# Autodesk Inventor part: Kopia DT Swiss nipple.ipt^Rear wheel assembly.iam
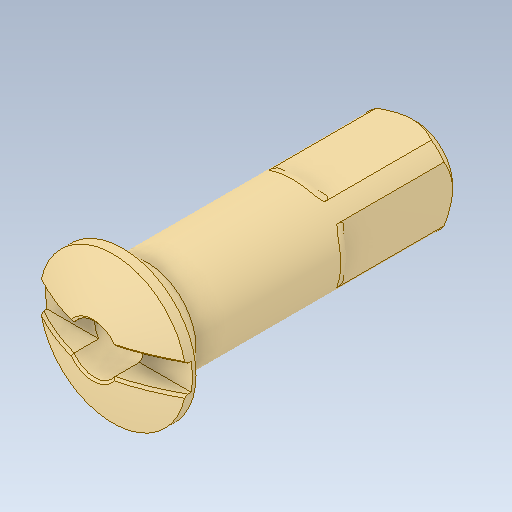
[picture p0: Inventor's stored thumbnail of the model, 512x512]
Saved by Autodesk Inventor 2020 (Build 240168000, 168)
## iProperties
Created: 2017-09
Part Number: Kopia DT Swiss nipple.ipt^Rear wheel assembly.iam
Material: Ogólny
Document SubType Name: Modeling
Designer: Tomasz
Density: 1 g/cm^3
Appearance: Domyślna
Sending System: SolidWorks 2017
Last Author: Tomasz
Last Saved: 2017-09-11
Author: Tomasz
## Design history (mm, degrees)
feature "DT Swiss nipple.ipt"
node "Bryła1"
